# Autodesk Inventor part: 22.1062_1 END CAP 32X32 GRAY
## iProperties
Created: 2007-01
Part Number: 22.1062_1 END CAP 32X32 GRAY
Document SubType Name: Modeling
Designer: Andy Moles
Material: ABS Plastic
Density: 1.06 g/cm^3
Mass: 3.18992 g
Surface Area: 23.4263 cm^2
Volume: 3.00936 cm^3
Author: Andy Moles
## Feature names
1. Extrusion1
2. Fillet1
3. Fillet2
4. Extrusion2
5. Fillet3
